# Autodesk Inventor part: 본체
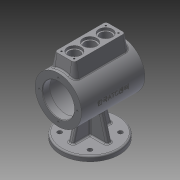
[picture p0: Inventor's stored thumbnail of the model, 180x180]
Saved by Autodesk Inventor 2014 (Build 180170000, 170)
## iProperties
Created: 2015-11
Part Number: 본체
Material: 알루미늄 6061
Document SubType Name: Modeling
Designer: mduedu
Density: 2.71 g/cm^3
Mass: 1433.84 g
Surface Area: 1290.15 cm^2
Volume: 529.094 cm^3
Appearance: 기본값
Author: mduedu
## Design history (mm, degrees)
sketch "스케치2"
  geometry: C1 r 47.5 at (0, 0); 1 further point
  constraints: 1 centre point, 1 coincident
  dimensions: "d147" = 95 diameter of C1
extrude "돌출1" new body sketch "스케치2" stored distance "d12" = 130; taper "d13" = 0 deg
feature "쉘1" dims "d31" = 15, "d32" = 6, "d33" = 15
sketch "스케치5"
  geometry: C1 r 32.5 at (0, 0); 1 further point
  constraints: 1 centre point, 1 coincident
  dimensions: "d34" = 65 diameter of C1
extrude "돌출3" cut sketch "스케치5" stored distance "d36" = 3; taper "d37" = 0 deg
node "작업 평면1"
sketch "스케치6"
  geometry: L1 (-60, -55)-(60, -55); L2 (60, -55)-(60, 55); L3 (60, 55)-(-60, 55); L4 (-60, 55)-(-60, -55); L5 (-60, -55)-(60, 55); L6 (60, -55)-(-60, 55); C1 r 60 at (0, 0); 1 further point
  constraints: 12 end point, 2 midpoint, 2 parallel, 1 centre point, 1 coincident, 1 horizontal, 1 perpendicular
  dimensions: "d41" = 110 distance of L3.end L1.start; "d43" = 120 distance of L2.end L3.end; "d199" = 120 diameter of C1
extrude "돌출4" join sketch "스케치6" distance "d44" = 10; taper "d45" = 0 deg
sketch "스케치19"
  geometry: L1 (-5, 40)-(5, 40); L2 (5, 40)-(5, -40); L3 (5, -40)-(-5, -40); L4 (-5, -40)-(-5, 40); L5 (-60, 55)-(-60, -55) reference; L6 (5, -40)-(-5, 40); L7 (5, 40)-(-5, -40); 3 further points
  constraints: 12 end point, 2 midpoint, 2 parallel, 1 coincident, 1 horizontal, 1 horizontal alignment, 1 perpendicular
  dimensions: "d151" = 10 distance of L1.start L1.end; "d152" = 80 distance of L3.end L1.start
extrude "돌출9" join sketch "스케치19" stored distance "d153" = 10; taper "d154" = 0 deg
feature "면 기울기2" dims angle "d198" = 15 deg
sketch "스케치20"
  geometry: L1 (65, 32.5)-(50, 32.5) reference; L2 (50, 32.5)-(50, 41.5) reference; L3 (50, 41.5)-(-50, 41.5) reference; L4 (-50, 41.5)-(-50, 32.5) reference; L5 (-50, 32.5)-(-65, 32.5) reference; L6 (-65, 32.5)-(-65, 47.5) reference; L7 (-65, 47.5)-(65, 47.5) reference; L8 (65, 47.5)-(65, 32.5) reference; L9 (50, -32.5)-(65, -32.5) reference; L10 (65, -32.5)-(65, -47.5) reference; L11 (65, -47.5)-(5, -47.5) reference; L12 (5, -47.5)-(5, -90) reference; L13 (5, -90)-(60, -90) reference; L14 (60, -100)-(-60, -100) reference; L15 (-60, -90)-(-5, -90) reference; L16 (-5, -90)-(-5, -47.5) reference; L17 (-5, -47.5)-(-65, -47.5) reference; L18 (-65, -47.5)-(-65, -32.5) reference; L19 (-65, -32.5)-(-50, -32.5) reference; L20 (-50, -32.5)-(-50, -41.5) reference; L21 (-50, -41.5)-(50, -41.5) reference; L22 (50, -41.5)-(50, -32.5) reference; L23 (-40, -90)-(-28.612, -47.5); L24 (60, -90)-(60, -100) reference; L25 (-60, -100)-(-60, -90) reference; 1 further point
  constraints: 2 end point, 2 point on line
  dimensions: "d156" = 105 deg angle of L23 L15; "d200" = 20 distance from line of L23.start L25
feature "리브2" sketch "스케치20" dims "d157" = 1, "d158" = 10, "d159" = 0, "d160" = 0, "d161" = 1, "d162" = 1
fillet "모깎기21" dims "d163" = 3
fillet "모깎기22" dims "d164" = 3
fillet "모깎기23" dims "d165" = 3
sketch "스케치21" dims "d166" = 78
  geometry: 3 further points
  constraints: 2 horizontal alignment, 1 coincident, 2 other
hole "구멍6" sketch "스케치21" at (39, 0) diameter "d168" = 3.242; stored, may be unused: countersink angle "d172" = 90 deg, drill point angle "d174" = 118 deg; dims "d169" = 9, "d170" = 4, "d171" = 2, "d173" = 11
node "작업 평면2"
sketch "스케치13"
  geometry: L1 (-52.5, -20)-(52.5, -20); L2 (52.5, -20)-(52.5, 20); L3 (52.5, 20)-(-52.5, 20); L4 (-52.5, 20)-(-52.5, -20); L5 (-52.5, -20)-(52.5, 20); L6 (52.5, -20)-(-52.5, 20); 1 further point
  constraints: 12 end point, 2 midpoint, 2 parallel, 1 horizontal, 1 perpendicular
  dimensions: "d93" = 105 distance of L2.end L3.end; "d95" = 40 distance of L1.end L2.end
extrude "돌출8" join sketch "스케치13" stored distance "d96" = 80; taper "d97" = 0 deg
fillet "모깎기15" dims "d98" = 5
feature "면 기울기1" dims angle "d178" = 10 deg
fillet "모깎기24" dims "d179" = 3
sketch "스케치14"
  geometry: L1 (-52.5, 15)-(-52.5, -15) reference; L2 (52.5, -15)-(52.5, 15) reference; L3 (-52.5, 0)-(52.5, 0); 4 further points
  constraints: 2 end point, 2 midpoint, 2 point on line, 1 coincident
  dimensions: "d100" = 32 distance of point (-32, 0) point (0, 0); "d102" = 32 distance of point (32, 0) point (0, 0) (derived)
hole "구멍3" sketch "스케치14" at (-32, 0), (0, 0), (32, 0) diameter "d103" = 22; stored, may be unused: countersink angle "d107" = 90 deg, drill point angle "d109" = 118 deg; dims "d104" = 8, "d105" = 28, "d106" = 5, "d108" = 10
sketch "스케치15"
  geometry: L1 (45.5, -13)-(-45.5, -13); L2 (-45.5, -13)-(-45.5, 13); L3 (-45.5, 13)-(45.5, 13); L4 (45.5, 13)-(45.5, -13); L5 (45.5, -13)-(-45.5, 13); L6 (-45.5, -13)-(45.5, 13); L7 (47.5, 20)-(-47.5, 20) reference; L8 (-52.5, 15)-(-52.5, -15) reference; 5 further points
  constraints: 12 end point, 4 coincident, 2 midpoint, 2 parallel, 1 horizontal, 1 perpendicular
  dimensions: "d110" = 7 distance between parallel lines of L3 L7; "d111" = 7 distance between parallel lines of L2 L8 (derived)
hole "구멍4" sketch "스케치15" at (-45.5, 13), (45.5, 13), (45.5, -13), (-45.5, -13) diameter "d112" = 3.242; stored, may be unused: countersink angle "d116" = 90 deg, drill point angle "d118" = 118 deg; dims "d113" = 10, "d114" = 28, "d115" = 5, "d117" = 13
node "작업 평면3"
chamfer "모따기2" distance "d183" = 1; stored, may be unused: second distance "d184" = 2, angle "d185" = 45 deg
fillet "모깎기26" dims "d194" = 3
sketch "스케치24"
  geometry: L1 (-31.113, -31.113)-(31.113, -31.113); L2 (31.113, -31.113)-(31.113, 31.113); L3 (31.113, 31.113)-(-31.113, 31.113); L4 (-31.113, 31.113)-(-31.113, -31.113); L5 (-31.113, -31.113)-(31.113, 31.113); L6 (31.113, -31.113)-(-31.113, 31.113); 1 further point
  constraints: 12 end point, 2 midpoint, 2 parallel, 2 perpendicular, 1 horizontal
  dimensions: "d201" = 88 distance of L1.start L2.end
hole "구멍8" sketch "스케치24" at (-31.113, -31.113), (31.113, 31.113), (31.113, -31.113), (-31.113, 31.113) diameter "d203" = 9; stored, may be unused: countersink angle "d207" = 90 deg, drill point angle "d209" = 118 deg; dims "d204" = 6, "d205" = 4, "d206" = 2, "d208" = 8
sketch "스케치22"
  geometry: 2 further points
  constraints: 1 coincident, 1 other
feature "엠보싱3" sketch "스케치22" dims "d31" = 15, "d93" = 105, "d95" = 40, "d181" = 0.5, "d182" = 0
node "솔리드1"
mirror "대칭6"
pattern_circular "원형 패턴2" dims angle "d176" = 360 deg
mirror "대칭5"
node "절단 모서리 투영1"
